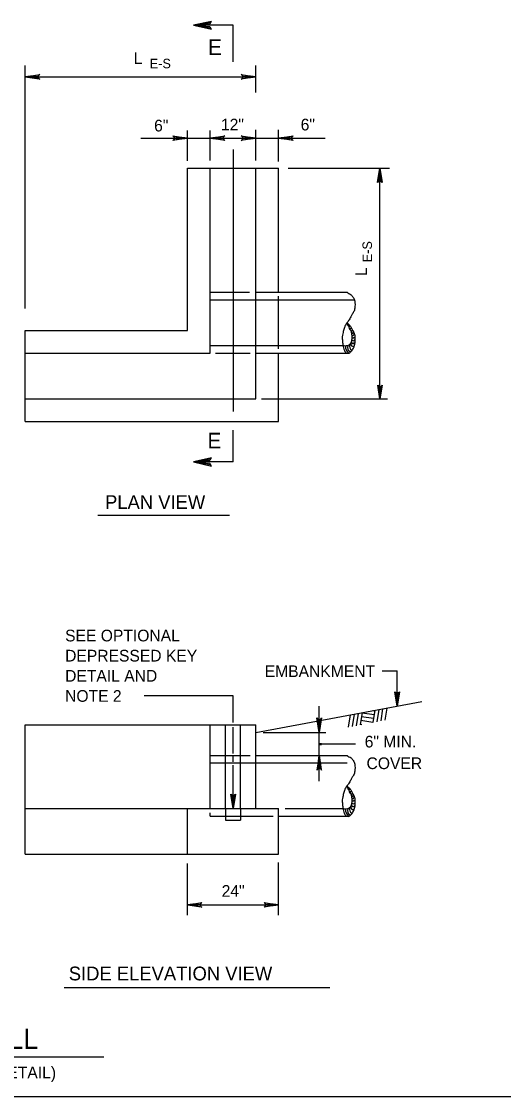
# Model space of a CAD drawing. Extents: x 638877 to 639960, y 297341 to 299123.
# Drawn here: x 639364.4 to 639488, y 297950.3 to 298225.8 of the extents above; entities that cross this region are included whole.
import ezdxf

# ---------------------------------------------------------------- set-up
doc = ezdxf.new("R2010")
doc.units = 0
for name, color, linetype in [('1', 7, 'Continuous'), ('2', 7, 'Continuous'), ('3', 7, 'Continuous')]:
    doc.layers.add(name, color=color, linetype=linetype)

msp = doc.modelspace()

# ---------------------------------------------------------------- linework, layer by layer
at = {"layer": '1'}
for p, q in [((639418.65, 298215.47), (639418.65, 298224.79)), ((639418.65, 298192.94), (639418.65, 298125.8)), ((639418.65, 298112.92), (639418.65, 298121.04)), ((639418.65, 298046.12), (639418.65, 298052.93)), ((639457.04, 298049.63), (639456.58, 298046.52)), ((639458.07, 298049.82), (639457.6, 298046.72)), ((639448.71, 298048.08), (639448.22, 298044.9)), ((639449.73, 298048.27), (639449.25, 298045.1)), ((639450.75, 298048.46), (639450.27, 298045.3)), ((639451.77, 298048.65), (639451.3, 298045.5)), ((639454.71, 298047.11), (639451.61, 298047.58)), ((639454.86, 298048.08), (639451.76, 298048.55)), ((639455, 298049.05), (639454.42, 298049.14)), ((639455, 298049.25), (639454.53, 298046.13)), ((639456.02, 298049.44), (639455.55, 298046.32)), ((639418.65, 298038.19), (639418.65, 298044.96)), ((639451.7, 298045.57), (639451.32, 298045.63)), ((639454.56, 298046.14), (639451.46, 298046.6)), ((639418.65, 298036.07), (639418.65, 298037.39)), ((639418.65, 298024.06), (639418.65, 298035.19)), ((638917.19, 297950.28), (639703.19, 297950.28))]:
    msp.add_line(p, q, dxfattribs=at)
at = {"layer": '2'}
for p, q in [((639418.65, 298224.79), (639408.51, 298224.79)), ((639365.35, 298152.18), (639365.35, 298214.45)), ((639424.5, 298207.57), (639424.5, 298214.45)), ((639365.35, 298211.56), (639424.5, 298211.56)), ((639394.97, 298195.88), (639412.8, 298195.88)), ((639406.95, 298190.04), (639406.95, 298197.87)), ((639412.8, 298190.18), (639412.8, 298197.87)), ((639412.8, 298195.88), (639424.5, 298195.88)), ((639424.5, 298190.18), (639424.5, 298198.02)), ((639424.5, 298195.88), (639442.33, 298195.88)), ((639430.35, 298189.89), (639430.35, 298198.02)), ((639406.95, 298146.62), (639406.95, 298188.22)), ((639406.95, 298188.22), (639430.35, 298188.22)), ((639412.8, 298140.77), (639412.8, 298188.22)), ((639424.5, 298129.07), (639424.5, 298188.22)), ((639430.35, 298156.37), (639430.35, 298188.22)), ((639432.83, 298188.22), (639458.81, 298188.22)), ((639456.35, 298129.07), (639456.35, 298188.22)), ((639412.8, 298156.37), (639422.89, 298156.37)), ((639412.8, 298154.42), (639449.64, 298154.42)), ((639424.5, 298156.37), (639447.9, 298156.37)), ((639430.35, 298141.85), (639430.35, 298155.41)), ((639365.35, 298146.62), (639406.95, 298146.62)), ((639365.35, 298123.22), (639365.35, 298146.62)), ((639365.35, 298140.77), (639412.8, 298140.77)), ((639412.8, 298142.72), (639446.88, 298142.72)), ((639414.12, 298140.77), (639423.05, 298140.77)), ((639424.5, 298140.77), (639447.9, 298140.77)), ((639430.35, 298123.22), (639430.35, 298140.77)), ((639365.35, 298129.07), (639424.5, 298129.07)), ((639425.95, 298129.07), (639458.24, 298129.07)), ((639365.35, 298123.22), (639430.35, 298123.22)), ((639418.65, 298112.92), (639408.51, 298112.92)), ((639456.92, 298059.4), (639460.72, 298059.4)), ((639460.72, 298050.29), (639460.72, 298059.4)), ((639418.65, 298052.93), (639395.87, 298052.93)), ((639424.5, 298043.56), (639467.12, 298051.49)), ((639440.78, 298043.56), (639440.78, 298050.32)), ((639365.35, 298012.36), (639365.35, 298045.51)), ((639365.35, 298045.51), (639424.5, 298045.51)), ((639412.8, 298024.06), (639412.8, 298045.51)), ((639416.7, 298024.06), (639416.7, 298045.51)), ((639420.6, 298024.06), (639420.6, 298045.51)), ((639424.5, 298024.06), (639424.5, 298045.51)), ((639426.4, 298043.56), (639442.45, 298043.56)), ((639440.78, 298037.84), (639440.78, 298043.56)), ((639440.78, 298040.7), (639450.06, 298040.7)), ((639412.8, 298037.71), (639423.05, 298037.71)), ((639412.8, 298035.76), (639447.9, 298035.76)), ((639424.5, 298037.71), (639447.9, 298037.71)), ((639440.78, 298031.08), (639440.78, 298037.84)), ((639365.35, 298024.06), (639430.35, 298024.06)), ((639406.95, 298012.36), (639406.95, 298024.06)), ((639412.8, 298022.11), (639412.8, 298022.97)), ((639412.8, 298022.11), (639428.97, 298022.11)), ((639416.7, 298024.06), (639416.7, 298021.13)), ((639420.6, 298024.06), (639420.6, 298021.13)), ((639430.35, 298012.36), (639430.35, 298024.06)), ((639430.35, 298022.11), (639447.9, 298022.11)), ((639432.01, 298024.06), (639446.88, 298024.06)), ((639416.7, 298021.13), (639420.6, 298021.13)), ((639365.35, 298012.36), (639430.35, 298012.36)), ((639406.95, 297996.76), (639406.95, 298009.97)), ((639430.35, 297996.76), (639430.35, 298010.25)), ((639406.95, 297999.37), (639430.35, 297999.37))]:
    msp.add_line(p, q, dxfattribs=at)
for points in [[(639412.87, 298225.52), (639412.71, 298225.09), (639408.51, 298224.79), (639412.87, 298225.52), (639413.09, 298225.77), (639408.51, 298224.79), (639412.7, 298224.51), (639412.86, 298224.09), (639408.51, 298224.79), (639413.09, 298223.82), (639412.86, 298224.09)], [(639368.89, 298211.11), (639368.76, 298211.37), (639365.35, 298211.56), (639368.89, 298211.11), (639369.07, 298210.96), (639365.35, 298211.56), (639368.76, 298211.73), (639368.88, 298211.98), (639365.35, 298211.56), (639369.07, 298212.15), (639368.88, 298211.98)], [(639420.96, 298212), (639421.09, 298211.74), (639424.5, 298211.56), (639420.96, 298212), (639420.78, 298212.16), (639424.5, 298211.56), (639421.09, 298211.39), (639420.97, 298211.14), (639424.5, 298211.56), (639420.78, 298210.96), (639420.97, 298211.14)], [(639403.41, 298196.33), (639403.54, 298196.07), (639406.95, 298195.88), (639403.41, 298196.33), (639403.23, 298196.48), (639406.95, 298195.88), (639403.54, 298195.71), (639403.42, 298195.46), (639406.95, 298195.88), (639403.23, 298195.29), (639403.42, 298195.46)], [(639416.34, 298195.44), (639416.21, 298195.7), (639412.8, 298195.88), (639416.34, 298195.44), (639416.52, 298195.28), (639412.8, 298195.88), (639416.21, 298196.05), (639416.33, 298196.3), (639412.8, 298195.88), (639416.52, 298196.48), (639416.33, 298196.3)], [(639420.96, 298196.33), (639421.09, 298196.07), (639424.5, 298195.88), (639420.96, 298196.33), (639420.78, 298196.48), (639424.5, 298195.88), (639421.09, 298195.71), (639420.97, 298195.46), (639424.5, 298195.88), (639420.78, 298195.29), (639420.97, 298195.46)], [(639433.89, 298195.44), (639433.76, 298195.7), (639430.35, 298195.88), (639433.89, 298195.44), (639434.07, 298195.28), (639430.35, 298195.88), (639433.76, 298196.05), (639433.88, 298196.3), (639430.35, 298195.88), (639434.07, 298196.48), (639433.88, 298196.3)], [(639455.91, 298184.68), (639456.16, 298184.82), (639456.35, 298188.22), (639455.91, 298184.68), (639455.75, 298184.5), (639456.35, 298188.22), (639456.52, 298184.82), (639456.77, 298184.69), (639456.35, 298188.22), (639456.94, 298184.5), (639456.77, 298184.69)], [(639456.77, 298132.38), (639456.53, 298132.26), (639456.35, 298129.07), (639456.77, 298132.38), (639456.91, 298132.55), (639456.35, 298129.07), (639456.19, 298132.25), (639455.96, 298132.37), (639456.35, 298129.07), (639455.8, 298132.55), (639455.96, 298132.37)], [(639412.87, 298113.72), (639412.71, 298113.26), (639408.51, 298112.92), (639412.87, 298113.72), (639413.09, 298113.99), (639408.51, 298112.92), (639412.7, 298112.61), (639412.86, 298112.16), (639408.51, 298112.92), (639413.09, 298111.85), (639412.86, 298112.16)], [(639461.16, 298053.83), (639460.91, 298053.7), (639460.72, 298050.29), (639461.16, 298053.83), (639461.32, 298054.02), (639460.72, 298050.29), (639460.55, 298053.7), (639460.3, 298053.82), (639460.72, 298050.29), (639460.13, 298054.02), (639460.3, 298053.82)], [(639441.23, 298047.1), (639440.97, 298046.96), (639440.78, 298043.56), (639441.23, 298047.1), (639441.38, 298047.28), (639440.78, 298043.56), (639440.61, 298046.96), (639440.36, 298047.09), (639440.78, 298043.56), (639440.19, 298047.28), (639440.36, 298047.09)], [(639441.23, 298034.11), (639440.97, 298034.24), (639440.78, 298037.65), (639441.23, 298034.11), (639441.38, 298033.92), (639440.78, 298037.65), (639440.61, 298034.24), (639440.36, 298034.12), (639440.78, 298037.65), (639440.19, 298033.92), (639440.36, 298034.12)], [(639419.1, 298027.6), (639418.84, 298027.46), (639418.65, 298024.06), (639419.1, 298027.6), (639419.25, 298027.78), (639418.65, 298024.06), (639418.48, 298027.46), (639418.23, 298027.59), (639418.65, 298024.06), (639418.06, 298027.78), (639418.23, 298027.59)], [(639410.49, 297998.93), (639410.36, 297999.19), (639406.95, 297999.37), (639410.49, 297998.93), (639410.67, 297998.77), (639406.95, 297999.37), (639410.36, 297999.54), (639410.48, 297999.79), (639406.95, 297999.37), (639410.67, 297999.97), (639410.48, 297999.79)], [(639426.81, 297999.82), (639426.94, 297999.56), (639430.35, 297999.37), (639426.81, 297999.82), (639426.63, 297999.97), (639430.35, 297999.37), (639426.94, 297999.2), (639426.82, 297998.95), (639430.35, 297999.37), (639426.63, 297998.78), (639426.82, 297998.95)]]:
    msp.add_lwpolyline(points, dxfattribs=at)
for centre, radius, start, end in [((639448.27, 298147.97), 0.127, 176.947, 93.053), ((639448.37, 298147.84), 0.298, 285.6074, 325.806), ((639448.76, 298147.22), 0.173, 195.7562, 33.8551), ((639449.09, 298146.69), 0.174, 203.3341, 43.8053), ((639449.35, 298146.11), 0.253, 188.5456, 52.8367), ((639449.52, 298143.16), 0.667, 173.2089, 278.5784), ((639449.48, 298143.65), 0.415, 171.0795, 335.4873), ((639449.42, 298145.61), 0.291, 223.7085, 2.3299), ((639449.6, 298144.31), 0.359, 199.7004, 348.5016), ((639449.55, 298145.03), 0.315, 212.411, 346.6825), ((639449.18, 298142.26), 1.67, 168.491, 237.5129), ((639449.17, 298142.24), 1.18, 158.8965, 245.9336), ((639449.67, 298142.62), 1.18, 164.8508, 242.5231), ((639448.27, 298029.3), 0.127, 176.947, 93.053), ((639448.37, 298029.17), 0.298, 285.6074, 325.806), ((639448.76, 298028.55), 0.173, 195.7562, 33.8551), ((639449.09, 298028.02), 0.174, 203.3341, 43.8053), ((639449.35, 298027.44), 0.253, 188.5456, 52.8367), ((639449.48, 298024.98), 0.415, 171.0795, 335.4873), ((639449.42, 298026.94), 0.291, 223.7085, 2.3299), ((639449.6, 298025.64), 0.359, 199.7004, 348.5016), ((639449.55, 298026.36), 0.315, 212.411, 346.6825), ((639449.18, 298023.59), 1.67, 168.491, 237.5129), ((639449.17, 298023.57), 1.18, 158.8965, 245.9336), ((639449.67, 298023.95), 1.18, 164.8508, 242.5231), ((639449.52, 298024.49), 0.667, 173.2089, 278.5784)]:
    msp.add_arc(centre, radius, start, end, dxfattribs=at)
for points in [[(639447.9, 298156.37), (639448.4, 298156.03), (639448.93, 298155.7), (639449.5, 298155.05), (639449.86, 298154.1), (639449.88, 298152.31), (639449.6, 298151.34), (639449.14, 298150.62), (639448.74, 298149.86), (639448.43, 298149.34), (639448.17, 298148.88), (639447.9, 298148.57), (639447.5, 298147.98), (639447.26, 298147.36), (639446.95, 298146.34), (639446.81, 298145.72), (639446.69, 298144.98), (639446.69, 298144.43), (639446.76, 298143.5), (639446.95, 298142.52), (639447.12, 298141.81), (639447.48, 298141.07), (639447.9, 298140.77), (639448.45, 298140.81), (639448.98, 298141.26), (639449.41, 298141.79), (639449.69, 298142.4), (639449.93, 298143.22), (639450, 298144.19), (639449.98, 298145), (639449.72, 298146), (639449.33, 298146.74), (639448.98, 298147.41), (639448.52, 298147.93), (639447.9, 298148.57)], [(639446.88, 298142.72), (639447.36, 298142.69), (639447.98, 298142.74), (639448.31, 298142.79), (639448.57, 298143.03), (639448.76, 298143.22), (639448.95, 298143.52), (639449.1, 298143.95), (639449.19, 298144.41), (639449.21, 298144.91), (639449.21, 298145.33), (639449.12, 298145.79), (639449.02, 298146.22), (639448.86, 298146.53), (639448.55, 298147.07), (639448.45, 298147.34), (639448.36, 298147.57), (639448.1, 298147.98), (639447.98, 298148.26), (639447.9, 298148.57)], [(639447.9, 298037.71), (639448.4, 298037.36), (639448.93, 298037.03), (639449.5, 298036.38), (639449.86, 298035.43), (639449.88, 298033.64), (639449.6, 298032.67), (639449.14, 298031.95), (639448.74, 298031.19), (639448.43, 298030.67), (639448.17, 298030.21), (639447.9, 298029.91), (639447.5, 298029.31), (639447.26, 298028.69), (639446.95, 298027.67), (639446.81, 298027.05), (639446.69, 298026.31), (639446.69, 298025.76), (639446.76, 298024.83), (639446.95, 298023.85), (639447.12, 298023.14), (639447.48, 298022.4), (639447.9, 298022.11), (639448.45, 298022.14), (639448.98, 298022.59), (639449.41, 298023.12), (639449.69, 298023.74), (639449.93, 298024.55), (639450, 298025.52), (639449.98, 298026.33), (639449.72, 298027.33), (639449.33, 298028.07), (639448.98, 298028.74), (639448.52, 298029.26), (639447.9, 298029.91)], [(639446.88, 298024.06), (639447.36, 298024.02), (639447.98, 298024.07), (639448.31, 298024.12), (639448.57, 298024.36), (639448.76, 298024.55), (639448.95, 298024.86), (639449.1, 298025.28), (639449.19, 298025.74), (639449.21, 298026.24), (639449.21, 298026.67), (639449.12, 298027.12), (639449.02, 298027.55), (639448.86, 298027.86), (639448.55, 298028.4), (639448.45, 298028.67), (639448.36, 298028.9), (639448.1, 298029.31), (639447.98, 298029.6), (639447.9, 298029.91)]]:
    msp.add_spline(points, degree=3, dxfattribs=at)
at = {"layer": '3'}
for p, q in [((639383.97, 298099.25), (639417.74, 298099.25)), ((639375.35, 297978.21), (639443.45, 297978.21)), ((639298.18, 297960.43), (639385.48, 297960.43))]:
    msp.add_line(p, q, dxfattribs=at)

# ---------------------------------------------------------------- texts
at = {"layer": '1'}
msp.add_text('E-S', height=2.43, dxfattribs=at).set_placement((639397.3, 298213.78))
msp.add_text('E-S', height=2.43, rotation=90, dxfattribs=at).set_placement((639454.3, 298164.07))
at = {"layer": '2'}
msp.add_text('L', height=3, rotation=90, dxfattribs=at).set_placement((639453.03, 298160.53))
msp.add_text('.', height=3.9, dxfattribs=at).set_placement((639440.39, 298040.28))
at = {"layer": '3'}
for s, height, p in [('E', 3.99, (639412.23, 298217.19)), ('L', 3, (639393.17, 298214.9)), ('E', 3.99, (639412.11, 298116.37)), ('PLAN VIEW', 3.53, (639385.82, 298100.84)), ('SEE OPTIONAL', 2.9999, (639375.58, 298066.91)), ('DEPRESSED KEY', 2.9999, (639375.58, 298061.75)), ('EMBANKMENT', 3, (639426.79, 298057.76)), ('DETAIL AND', 3, (639375.58, 298056.59)), ('NOTE 2', 3, (639375.58, 298051.43)), ('6" MIN.', 3, (639452.43, 298039.72)), ('COVER', 3, (639452.9, 298034.18)), ('24"', 3, (639415.74, 298001.46)), ('SIDE ELEVATION VIEW', 3.5299, (639376.52, 297980.04)), ('TYPE E-S ENDWALL', 5.1858, (639301.66, 297962.46)), ('(WITH OPTIONAL DEPRESSED KEY DETAIL)', 2.9999, (639288.77, 297954.91))]:
    msp.add_text(s, height=height, dxfattribs=at).set_placement(p)
for s, p in [('6"', (639398.41, 298197.59)), ('12"', (639415.56, 298197.85)), ('6"', (639436.01, 298197.85))]:
    msp.add_text(s, height=3, rotation=360, dxfattribs=at).set_placement(p)

doc.saveas('drawing.dxf')
